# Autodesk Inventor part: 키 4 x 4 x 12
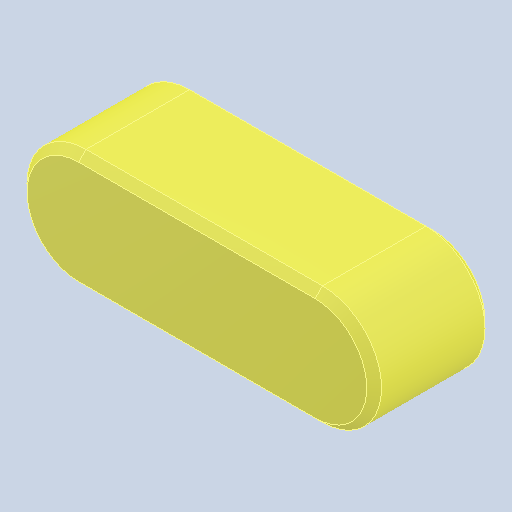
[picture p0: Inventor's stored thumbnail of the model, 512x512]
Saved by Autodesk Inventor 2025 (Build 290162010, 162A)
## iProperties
Created: 2024-07
Part Number: 키 4 x 4 x 12
Material: 강철, 연강
Description: 키 및 해당 키홈
Document SubType Name: Modeling
Designer: Admin
Density: 7.85 g/cm^3
Appearance: 기본값
Author: jhkim
Sending System: Autodesk Inventor 2025
Preprocessor: ST-DEVELOPER v20
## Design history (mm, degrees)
feature "Solid1"
node "솔리드1"
